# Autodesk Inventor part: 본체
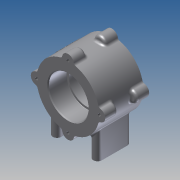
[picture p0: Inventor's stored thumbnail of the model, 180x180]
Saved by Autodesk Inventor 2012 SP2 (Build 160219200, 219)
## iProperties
Created: 2015-03
Part Number: 본체
Material: Default
Document SubType Name: Modeling
Designer: Administrator
Density: 1 g/cm^3
Author: Administrator
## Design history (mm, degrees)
sketch "스케치1"
  geometry: C1 r 37 at (0, 0); 1 further point
  constraints: 1 centre point, 1 coincident
  dimensions: "d0" = 74 diameter of C1
extrude "돌출1" new body sketch "스케치1" distance "d1" = 26; taper "d3" = 0 deg; dims "d2" = 26, "d4" = 0
sketch "스케치2"
  geometry: A1 r 37 centre (0, 0) between (0, 37) and (-6.969, 36.338) reference; A2 r 7 centre (0, 37) between (6.969, 36.338) and (-6.969, 36.338)
  constraints: 5 point on circle, 1 centre point, 1 coincident, 1 vertical alignment
  dimensions: "d5" = 14 diameter of A2
extrude "돌출2" join sketch "스케치2" distance "d6" = 15; taper "d7" = 0 deg
fillet "모깎기1" dims "d8" = 3
sketch "스케치3"
  geometry: A1 r 37 centre (0, 0) between (35.863, 9.104) and (9.104, 35.863) reference; 1 further point
  constraints: 1 coincident
hole "구멍1" sketch "스케치3" at (0, 0) diameter "d12" = 47; stored, may be unused: countersink angle "d16" = 90 deg, drill point angle "d18" = 0 deg; dims "d13" = 6, "d14" = 4, "d15" = 2, "d17" = 22
sketch "스케치4"
  geometry: C1 r 23.5 at (0, 0) reference; 1 further point
  constraints: 1 coincident
hole "구멍2" sketch "스케치4" at (0, 0) diameter "d19" = 42; stored, may be unused: countersink angle "d23" = 90 deg, drill point angle "d25" = 0 deg; dims "d20" = 6, "d21" = 4, "d22" = 2, "d24" = 22
node "작업 평면2"
sketch "스케치5"
  geometry: L1 (-6.889, 26)-(6.889, 26) reference; L2 (-6.889, -26)-(6.889, -26) reference; L3 (35.863, -26)-(9.104, -26) reference; L4 (-9.104, -26)-(-35.863, -26) reference; L5 (-35.863, 26)-(-9.104, 26) reference; L6 (9.104, 26)-(35.863, 26) reference; L7 (37, -11)-(37, 11) reference; L8 (-37, -11)-(-37, 11) reference; L9 (0, 26)-(0, -26); L10 (-37, 0)-(37, 0); L11 (19, -15)-(19, 15); L12 (29, -15)-(29, 15); L13 (-19, -15)-(-19, 15); L14 (-29, -15)-(-29, 15); A1 r 5 centre (24, -15) between (19, -15) and (29, -15); A2 r 5 centre (24, 15) between (29, 15) and (19, 15); A3 r 5 centre (-24, -15) between (-29, -15) and (-19, -15); A4 r 5 centre (-24, 15) between (-19, 15) and (-29, 15); 2 further points
  constraints: 12 end point, 8 point on circle, 6 symmetric about line, 4 centre point, 4 midpoint, 2 tangent, 1 coincident, 1 parallel, 1 perpendicular, 1 vertical alignment, 2 other
  dimensions: "d28" = 24 distance from line of point (24, -15) L9; "d29" = 15 distance from line of L10 point (24, -15); "d30" = 10 diameter of A1; "d31" = 10 diameter of A2; "d32" = 30 distance of A2.centre A1.centre
extrude "돌출3" join sketch "스케치5" stored distance "d33" = 15; taper "d34" = 0 deg
sketch "스케치6"
  geometry: A1 r 7 centre (0, 37) between (6.889, 38.239) and (-6.889, 38.239) reference; 1 further point
  constraints: 1 coincident
hole "구멍3" sketch "스케치6" at (0, 37) diameter "d35" = 3.459; stored, may be unused: countersink angle "d39" = 90 deg, drill point angle "d41" = 118 deg; dims "d36" = 8, "d37" = 4, "d38" = 2, "d40" = 11
sketch "스케치7"
  geometry: A1 r 7 centre (0, -37) between (-6.889, -38.239) and (6.889, -38.239) reference; 1 further point
  constraints: 1 coincident
hole "구멍4" sketch "스케치7" at (0, -37) diameter "d45" = 3.459; stored, may be unused: countersink angle "d49" = 90 deg, drill point angle "d51" = 118 deg; dims "d46" = 8, "d47" = 4, "d48" = 2, "d50" = 11
sketch "스케치8"
  geometry: A1 r 5 centre (-24, -15) between (-29, -15) and (-19, -15) reference; A2 r 5 centre (-24, 15) between (-19, 15) and (-29, 15) reference; 3 further points
  constraints: 2 coincident
hole "구멍5" sketch "스케치8" at (-24, 15), (-24, -15) diameter "d55" = 4.459; stored, may be unused: countersink angle "d59" = 90 deg, drill point angle "d61" = 118 deg; dims "d56" = 6, "d57" = 4, "d58" = 2, "d60" = 8
fillet "모깎기2" dims "d62" = 0.3
chamfer "모따기1" distance "d63" = 1; stored, may be unused: second distance "d64" = 2, angle "d65" = 45 deg
fillet "모깎기3" dims "d66" = 3
fillet "모깎기4" dims "d67" = 3
sketch "스케치10"
  geometry: L1 (0, 0)-(24.5, 0); L2 (0, 0)-(26.163, 26.163); L3 (24.335, 27.871)-(24.466, 28.001); L4 (24.466, 28.001)-(28.001, 24.466); L5 (28.001, 24.466)-(27.871, 24.335); A1 r 37 centre (0, 0) between (35.863, 9.104) and (9.104, 35.863) reference; 1 further point
  constraints: 10 end point, 3 point on circle, 2 parallel, 1 horizontal, 1 horizontal alignment, 1 perpendicular, 2 other
  dimensions: "d68" = 45 deg angle of L2 L1; "d69" = 0.1 distance from line of L4 L2.end; "d70" = 5 distance of L3.end L4.end
extrude "돌출4" join sketch "스케치10" distance "d71" = 26; taper "d73" = 0 deg; dims "d72" = 26, "d74" = 0
sketch "스케치11"
  geometry: L1 (5, 52)-(0, 52) reference; L2 (0, 0)-(5, 0) reference; L3 (0, 39)-(0, 13); L4 (0, 13)-(5, 13); L5 (5, 13)-(5, 39); L6 (5, 39)-(0, 39); 3 further points
  constraints: 2 midpoint, 1 horizontal, 1 vertical alignment, 2 other
  dimensions: "d75" = 5 distance of L5.end L3.start; "d76" = 26 distance of L4.end L5.end; "d78" = 13 distance between parallel lines of L2 L4
feature "엠보싱1" sketch "스케치11" dims "d79" = 0.4, "d80" = 0
node "솔리드1"
pattern_circular "원형 패턴1" dims angle "d10" = 360 deg
mirror "대칭2"
mirror "대칭3"
pattern_circular "원형 패턴2" dims angle "d43" = 360 deg
pattern_circular "원형 패턴3" dims angle "d53" = 360 deg
mirror "대칭4"
other parameters: "d27" = -56
